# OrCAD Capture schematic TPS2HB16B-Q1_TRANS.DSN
size E; title: TPS2HB16B-Q1 40-V, 16-mOhm Dual-Channel Smart High-; rev: 1.0; note: Datasheet: SLVSDV7C     EVM: NA; note: Side Switch
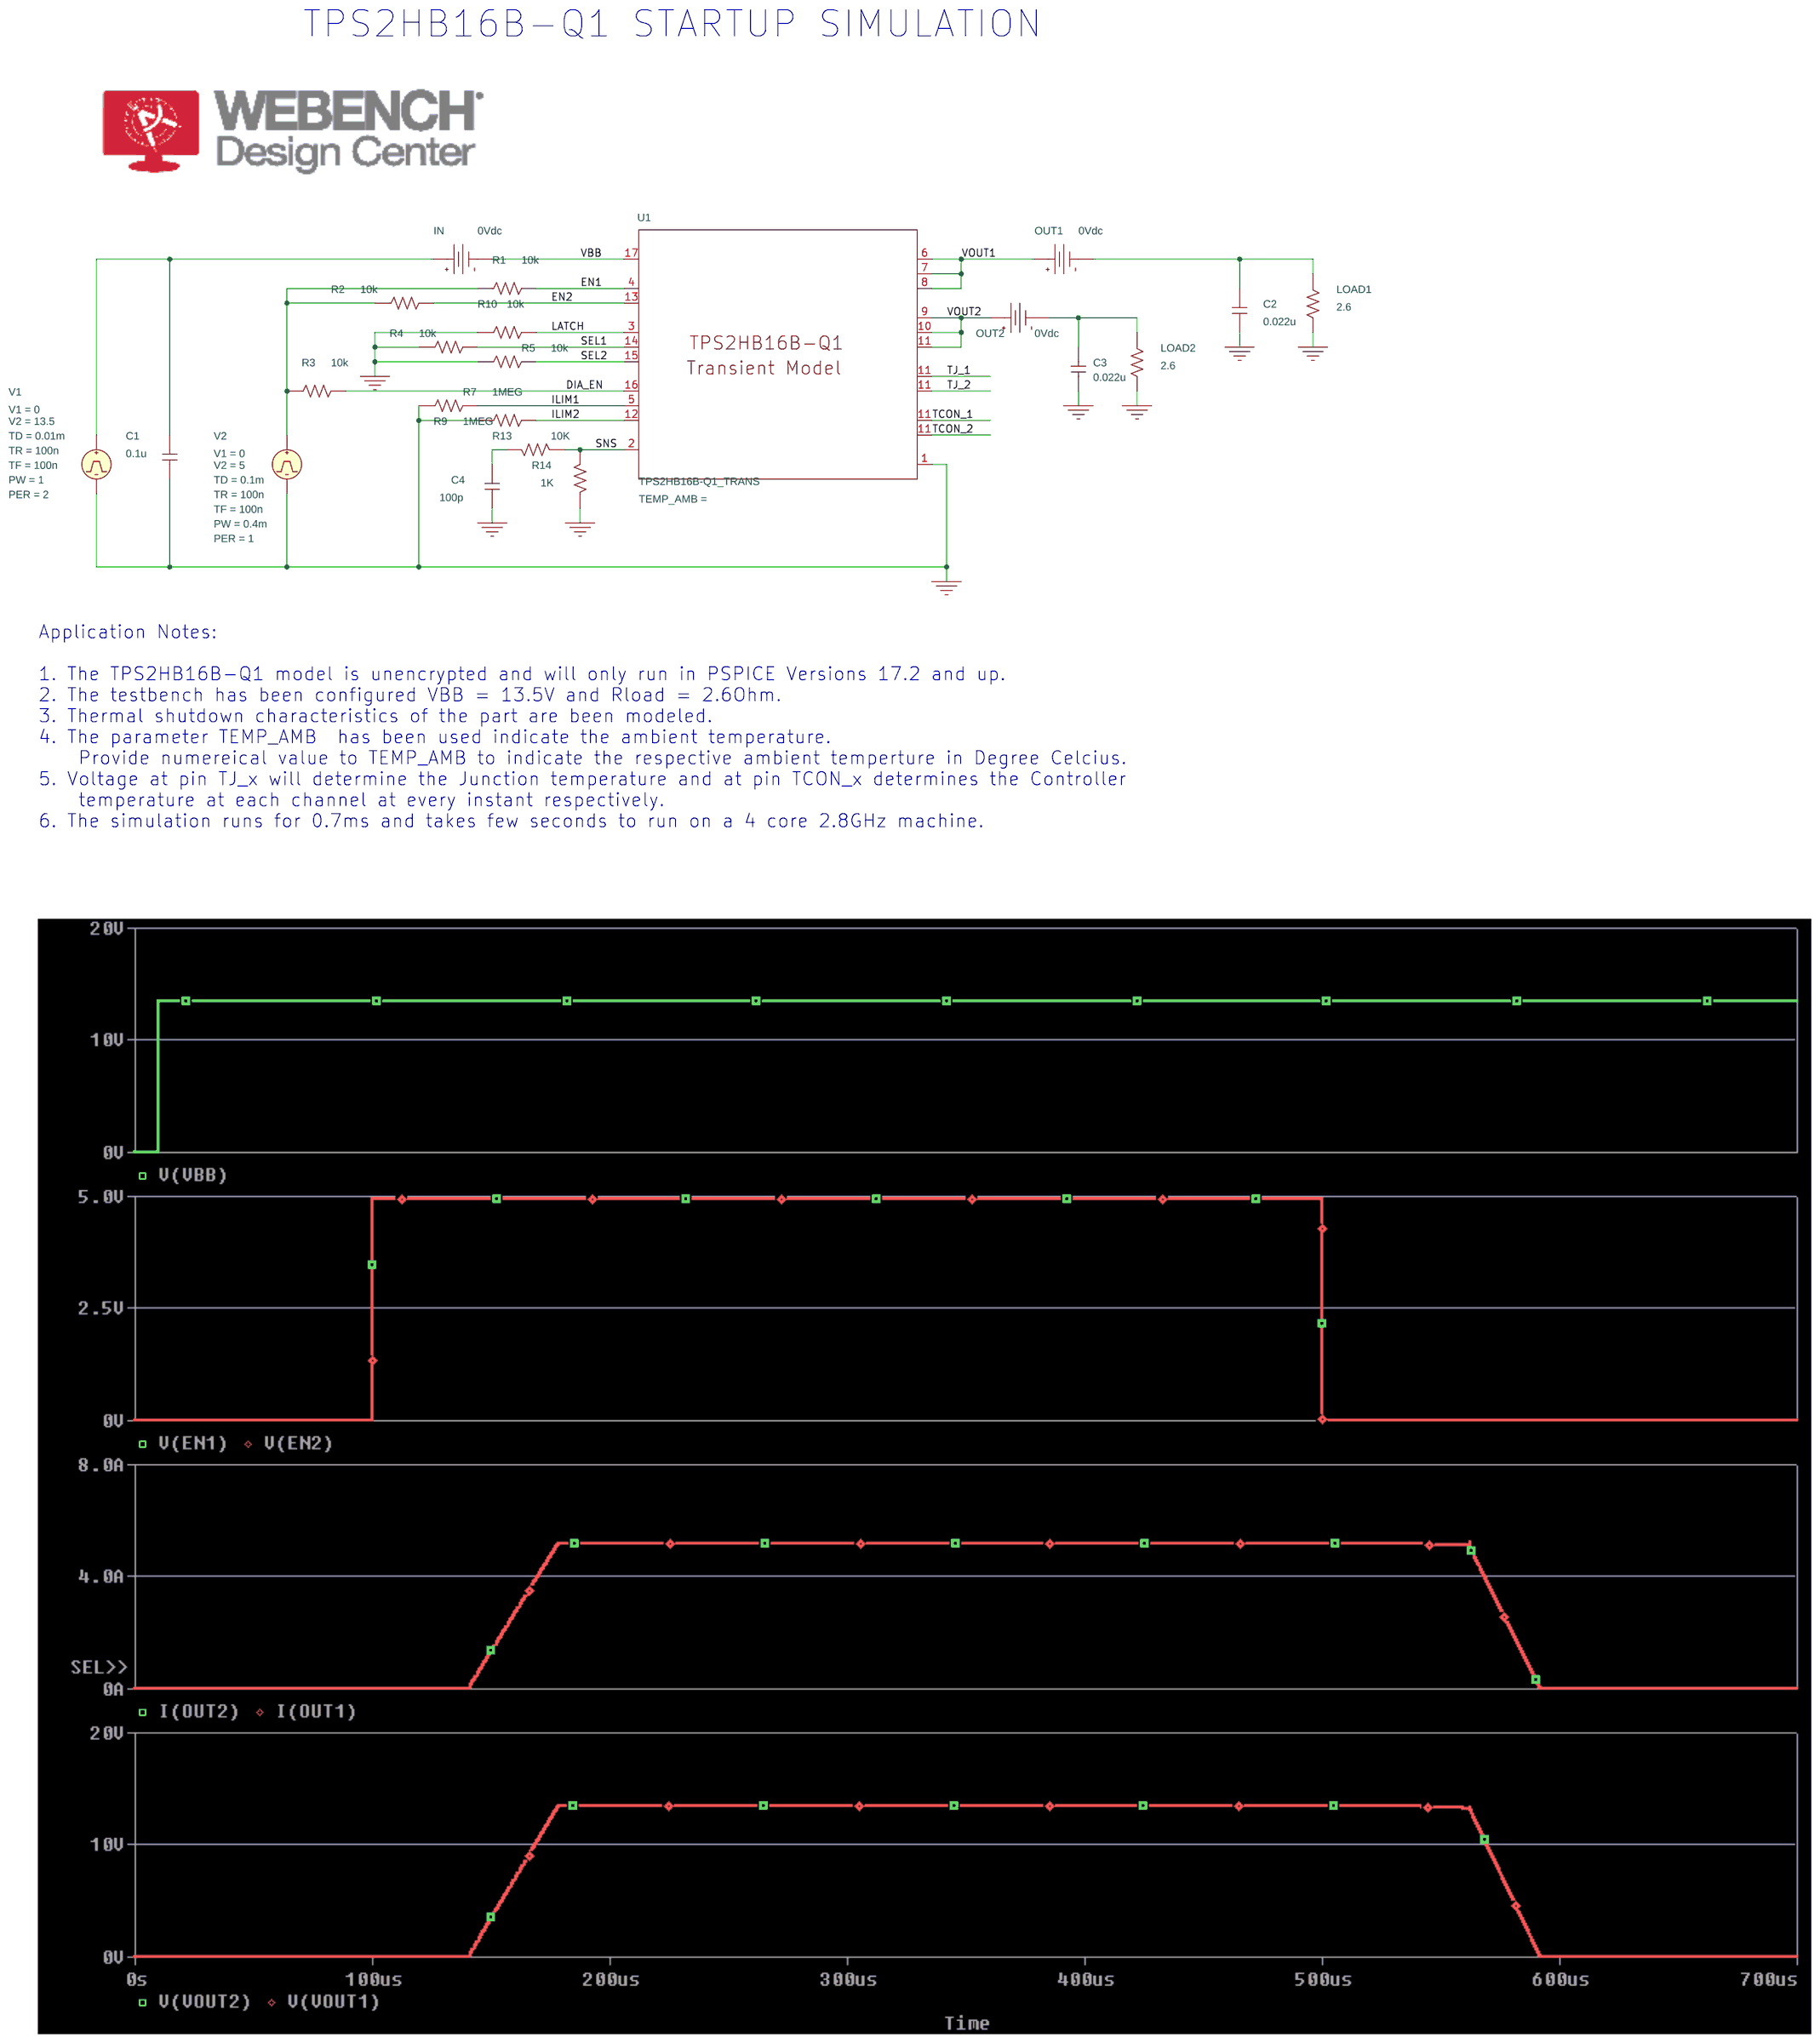
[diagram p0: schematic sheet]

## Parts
C1  0.1u  [RAD/CK05]
C2  0.022u  [RAD/CK05]
C3  0.022u  [RAD/CK05]
C4  100p  [RAD/CK05]
IN  VDC
LOAD1  2.6  [AX/RC05]
LOAD2  2.6  [AX/RC05]
OUT1  VDC
OUT2  VDC
R1  10k  [AX/RC05]
R2  10k  [AX/RC05]
R3  10k  [AX/RC05]
R4  10k  [AX/RC05]
R5  10k  [AX/RC05]
R7  1MEG  [AX/RC05]
R9  1MEG  [AX/RC05]
R10  10k  [AX/RC05]
R13  10K  [AX/RC05]
R14  1K  [AX/RC05]
U1  TPS2HB16B-Q1_TRANS  [PWP0016M_N]
V1  VPULSE
V2  VPULSE

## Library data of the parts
C1-C4 = C
IN OUT1 OUT2 = VDC: DC: 0Vdc
LOAD1 LOAD2 R1-R5 R7 R9 R10 R13 R14 = R
U1 = TPS2HB16B-Q1_TRANS
V1 = VPULSE: PER: 2; PW: 1; TD: 0.01m; TF: 100n; TR: 100n; V1: 0; V2: 13.5
V2 = VPULSE: PER: 1; PW: 0.4m; TD: 0.1m; TF: 100n; TR: 100n; V1: 0; V2: 5

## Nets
0: C1.2 C2.2 C3.2 C4.2 LOAD1.2 LOAD2.2 R4.1 R5.1 R7.1 R9.1 R10.1 R14.1 U1.1(GND) V1.2(-) V2.2(-)
DIA_EN: R3.2 U1.16(DIA_EN)
EN1: R1.2 U1.4(EN1)
EN2: R2.2 U1.13(EN2)
ILIM1: R7.2 U1.5(ILIM1)
ILIM2: R9.2 U1.12(ILIM2)
LATCH: R10.2 U1.3(LATCH)
SEL1: R4.2 U1.14(SEL1)
SEL2: R5.2 U1.15(SEL2)
SNS: R13.1 R14.2 U1.2(SNS)
TCON_1: OUT2.0(+) U1.9(VOUT2_0) U1.10(VOUT2_1) U1.11(TCON_2)
VBB: IN.1(-) U1.17(VBB)
VOUT1: OUT1.0(+) U1.6(VOUT1_0) U1.7(VOUT1_1) U1.8(VOUT1_2)
N16777455: C1.1 IN.0(+) V1.1(+)
N16777503: R1.1 R2.1 R3.1 V2.1(+)
N16777783: C4.1 R13.2
N16778202: C2.1 LOAD1.1 OUT1.1(-)
N16778253: C3.1 LOAD2.1 OUT2.1(-)

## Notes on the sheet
- TPS2HB16B-Q1 STARTUP SIMULATION
- Application Notes:
  1. The TPS2HB16B-Q1 model is unencrypted and will only run in PSPICE Versions 17.2 and up.
  2. The testbench has been configured VBB = 13.5V and Rload = 2.6Ohm.
  3. Thermal shutdown characteristics of the part are been modeled.
  4. The parameter TEMP_AMB  has been used indicate the ambient temperature.
      Provide numereical value to TEMP_AMB to indicate the respective ambient temperture in Degree Celcius.
  5. Voltage at pin TJ_x will determine the Junction temperature and at pin TCON_x determines the Controller
      temperature at each channel at every instant respectively.
  6. The simulation runs for 0.7ms and takes few seconds to run on a 4 core 2.8GHz machine.
